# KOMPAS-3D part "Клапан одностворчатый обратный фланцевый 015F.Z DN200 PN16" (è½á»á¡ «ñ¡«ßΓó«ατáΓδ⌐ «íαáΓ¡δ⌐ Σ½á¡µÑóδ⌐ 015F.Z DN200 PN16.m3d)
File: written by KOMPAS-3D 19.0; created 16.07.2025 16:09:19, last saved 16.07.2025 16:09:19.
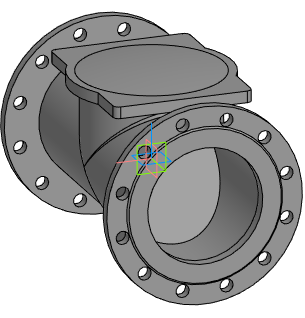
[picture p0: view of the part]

Document properties: Полное имя файла: E:\Dendor Работа Сачек\3D для проектировщиков\5.4 Тип 015F.Z. Клапан одностворчатый обратный фланцевый\stp_Клапан одностворчатый обратный фланцевый 015F.Z PN10_16\Клапан одностворчатый обратный фланцевый 015F.Z DN200 PN16.m3d

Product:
- Part/product: Клапан одностворчатый обратный фланцевый 015F.Z DN200 PN16

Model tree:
1. Операция без истории:1  (labels: Клапан одностворчатый обратный фланцевый 015F.Z DN200 PN16)
2. Операция без истории:2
